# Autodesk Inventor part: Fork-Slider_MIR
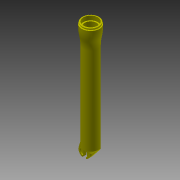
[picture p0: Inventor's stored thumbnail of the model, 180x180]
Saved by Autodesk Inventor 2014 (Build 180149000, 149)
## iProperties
Created: 2001-11
Part Number: Fork-Slider_MIR
Document SubType Name: Modeling
Designer: Autodesk, Inc.
Mass: 115.052 g
Surface Area: 625.893 cm^2
Volume: 115.052 cm^3
Density: 1 g/cm^3
Material: Generic
Appearance: Yellow (Flat)
Author: Autodesk, Inc.
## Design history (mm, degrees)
derived "Fork-Slider.ipt"
  node "Sketch7"
  node "Sketch9"
  sketch "Sketch13"
    geometry: C1 r 3.034 at (0, 0) reference; A1 r 3.034 centre (0, 0) between (-2.458, 1.778) and (2.458, 1.778) reference
  workplane "Work Plane3"
  node "WorkPlane4"
  workplane "Work Plane8"
  node "WorkPlane5"
  node "WorkPlane1"
  node "WorkPlane2"
  node "WorkPlane3"
  node "WorkAxis1"
body "Solid1"
tag "TaggingFeature2"
workplane "Work Plane10"
workplane "Work Plane11"
workplane "Work Plane5"
workplane "Work Plane6"
feature "DerivedBody::Fork-Slider.ipt"
